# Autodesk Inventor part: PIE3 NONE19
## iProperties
Shininess: 64.0
Length Units: 11269
Angle Units: 11279
Time Units: 11290
Mass Units: 11286
Length Display Precision: 3
Angle Display Precision: 2
Compacted: True
Part Number: PIE3 NONE19
Document SubType Name: Modeling
Created: 2004-08
Designer: John Blackburn
Manufacturer: Standard
Standards Organization: Custom
Density: 0.0
Volumn: 0.0
Area: 0.0
PropertySet Name: Model Information
Control State: 0
Master: False
Checked Out: False
Author: John Blackburn
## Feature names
1. Erst1
